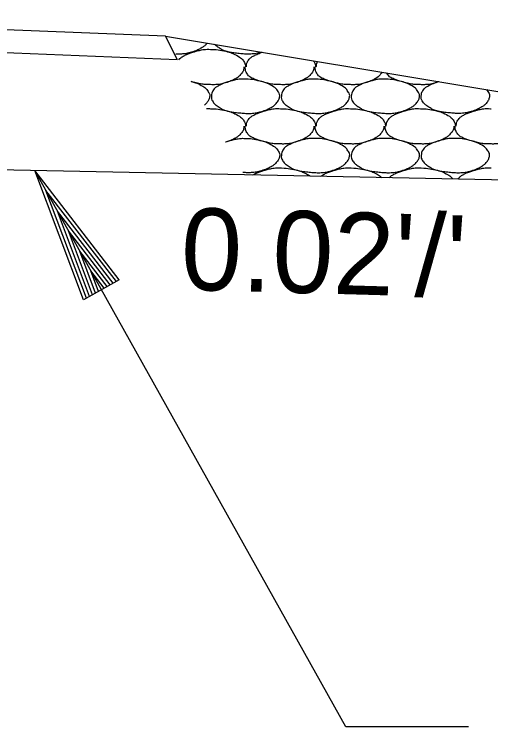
# Model space of a CAD drawing. Extents: x -900 to 15312, y 1857 to 2945.
# Drawn here: x 4203.1 to 4238, y 2407.3 to 2459.5 of the extents above; entities that cross this region are included whole.
import ezdxf

# ---------------------------------------------------------------- set-up
doc = ezdxf.new("R2010")
doc.units = 0
doc.layers.add('R_Annotation', color=7, linetype='Continuous')
doc.layers.add('R_Dimension', color=7, linetype='Continuous')

msp = doc.modelspace()

# ---------------------------------------------------------------- linework, layer by layer
at = {"layer": 'R_Annotation'}
for p, q in [((4214.164, 2457.891), (4174.164, 2459.491)), ((4214.164, 2457.891), (4215.015, 2456.189)), ((4214.164, 2457.891), (4374.164, 2431.224)), ((4282.587, 2446.487), (4064.164, 2450.856))]:
    msp.add_line(p, q, dxfattribs=at)
for points in [[(4217.21, 2457.383), (4217.184, 2457.347), (4217.061, 2457.195), (4216.938, 2457.101), (4216.622, 2456.922), (4216.424, 2456.826), (4215.92, 2456.667), (4215.636, 2456.595), (4215.199, 2456.568), (4215.054, 2456.567), (4214.909, 2456.576)], [(4221.199, 2456.718), (4220.957, 2456.647), (4220.714, 2456.592), (4220.317, 2456.567), (4219.95, 2456.577), (4219.584, 2456.612), (4219.122, 2456.663), (4218.883, 2456.701), (4218.448, 2456.802), (4218.279, 2456.907), (4217.97, 2457.101), (4217.853, 2457.183), (4217.748, 2457.294)], [(4215.144, 2456.163), (4215.25, 2456.298), (4215.379, 2456.381), (4215.656, 2456.525), (4215.785, 2456.59), (4216.123, 2456.704), (4216.321, 2456.764), (4216.65, 2456.849), (4216.958, 2456.921), (4217.278, 2456.933), (4217.464, 2456.917)], [(4217.464, 2456.917), (4217.484, 2456.915), (4217.504, 2456.918), (4217.524, 2456.917)], [(4217.524, 2456.917), (4217.817, 2456.921), (4218.111, 2456.876), (4218.762, 2456.743), (4219.092, 2456.635), (4219.645, 2456.338), (4219.822, 2456.183), (4219.996, 2455.859), (4220.016, 2455.76), (4220.024, 2455.65), (4220.025, 2455.643), (4220.024, 2455.637)], [(4220.084, 2455.637), (4220.084, 2455.643), (4220.086, 2455.819), (4220.135, 2455.987), (4220.354, 2456.288), (4220.49, 2456.376), (4220.776, 2456.525), (4220.905, 2456.59), (4221.117, 2456.661), (4221.19, 2456.685), (4221.263, 2456.708)], [(4224.982, 2456.088), (4225.011, 2456.047), (4225.107, 2455.907), (4225.136, 2455.76), (4225.144, 2455.65), (4225.145, 2455.643), (4225.144, 2455.637)], [(4219.904, 2455.637), (4219.904, 2455.617), (4219.909, 2455.391), (4219.768, 2455.198), (4219.533, 2454.935), (4219.438, 2454.861), (4219.122, 2454.682), (4218.924, 2454.586), (4218.42, 2454.427), (4218.137, 2454.348), (4217.717, 2454.332), (4217.59, 2454.331), (4217.464, 2454.337)], [(4222.584, 2454.337), (4222.557, 2454.337), (4222.31, 2454.334), (4222.063, 2454.357), (4221.61, 2454.439), (4221.387, 2454.51), (4220.964, 2454.632), (4220.774, 2454.695), (4220.372, 2454.868), (4220.196, 2455.021), (4220.026, 2455.347), (4220.004, 2455.46), (4220.004, 2455.597), (4220.004, 2455.617), (4220.004, 2455.637)], [(4225.024, 2455.637), (4225.024, 2455.617), (4225.029, 2455.391), (4224.888, 2455.198), (4224.653, 2454.935), (4224.558, 2454.861), (4224.242, 2454.682), (4224.044, 2454.586), (4223.54, 2454.427), (4223.257, 2454.348), (4222.837, 2454.332), (4222.71, 2454.331), (4222.584, 2454.337)], [(4227.704, 2454.337), (4227.677, 2454.337), (4227.43, 2454.334), (4227.183, 2454.357), (4226.73, 2454.439), (4226.507, 2454.51), (4226.084, 2454.632), (4225.894, 2454.695), (4225.492, 2454.868), (4225.316, 2455.021), (4225.146, 2455.347), (4225.124, 2455.46), (4225.124, 2455.597), (4225.124, 2455.617), (4225.124, 2455.637)], [(4225.204, 2455.637), (4225.204, 2455.643), (4225.205, 2455.781), (4225.236, 2455.915), (4225.3, 2456.035)], [(4230.028, 2455.247), (4229.981, 2455.174), (4229.924, 2455.104), (4229.773, 2454.935), (4229.678, 2454.861), (4229.362, 2454.682), (4229.164, 2454.586), (4228.66, 2454.427), (4228.377, 2454.348), (4227.957, 2454.332), (4227.83, 2454.331), (4227.704, 2454.337)], [(4232.824, 2454.337), (4232.797, 2454.337), (4232.55, 2454.334), (4232.303, 2454.357), (4231.85, 2454.439), (4231.627, 2454.51), (4231.204, 2454.632), (4231.014, 2454.695), (4230.626, 2454.861), (4230.46, 2455), (4230.347, 2455.194)], [(4216.044, 2454.576), (4216.304, 2454.506), (4216.554, 2454.411), (4217.025, 2454.158), (4217.177, 2453.997), (4217.387, 2453.682), (4217.421, 2453.572), (4217.37, 2453.289), (4217.272, 2453.102), (4217.092, 2452.901), (4217.06, 2452.869), (4217.028, 2452.84)], [(4217.464, 2454.337), (4217.437, 2454.337), (4217.19, 2454.334), (4216.943, 2454.357), (4216.492, 2454.438), (4216.27, 2454.509), (4216.044, 2454.574)], [(4220.024, 2454.737), (4220.317, 2454.741), (4220.611, 2454.696), (4221.262, 2454.563), (4221.592, 2454.455), (4222.145, 2454.158), (4222.297, 2453.997), (4222.507, 2453.682), (4222.541, 2453.572), (4222.49, 2453.289), (4222.392, 2453.102), (4222.15, 2452.832), (4222.058, 2452.761), (4221.742, 2452.582), (4221.544, 2452.486), (4221.04, 2452.327), (4220.756, 2452.255), (4220.317, 2452.227), (4219.95, 2452.237), (4219.584, 2452.272), (4219.122, 2452.323), (4218.883, 2452.361), (4218.448, 2452.462), (4218.279, 2452.567), (4217.905, 2452.801), (4217.744, 2452.922), (4217.532, 2453.247), (4217.517, 2453.365), (4217.533, 2453.639), (4217.567, 2453.802), (4217.802, 2454.113), (4217.93, 2454.196), (4218.216, 2454.345), (4218.345, 2454.41), (4218.683, 2454.524), (4218.881, 2454.584), (4219.21, 2454.669), (4219.518, 2454.741), (4219.838, 2454.753), (4220.024, 2454.737)], [(4225.144, 2454.737), (4225.437, 2454.741), (4225.731, 2454.696), (4226.382, 2454.563), (4226.712, 2454.455), (4227.265, 2454.158), (4227.417, 2453.997), (4227.627, 2453.682), (4227.661, 2453.572), (4227.61, 2453.289), (4227.512, 2453.102), (4227.27, 2452.832), (4227.178, 2452.761), (4226.862, 2452.582), (4226.664, 2452.486), (4226.16, 2452.327), (4225.876, 2452.255), (4225.437, 2452.227), (4225.07, 2452.237), (4224.704, 2452.272), (4224.242, 2452.323), (4224.003, 2452.361), (4223.568, 2452.462), (4223.399, 2452.567), (4223.025, 2452.801), (4222.864, 2452.922), (4222.652, 2453.247), (4222.637, 2453.365), (4222.653, 2453.639), (4222.687, 2453.802), (4222.922, 2454.113), (4223.05, 2454.196), (4223.336, 2454.345), (4223.465, 2454.41), (4223.803, 2454.524), (4224.001, 2454.584), (4224.33, 2454.669), (4224.638, 2454.741), (4224.958, 2454.753), (4225.144, 2454.737)], [(4230.264, 2454.737), (4230.557, 2454.741), (4230.851, 2454.696), (4231.502, 2454.563), (4231.832, 2454.455), (4232.385, 2454.158), (4232.537, 2453.997), (4232.747, 2453.682), (4232.781, 2453.572), (4232.73, 2453.289), (4232.632, 2453.102), (4232.39, 2452.832), (4232.298, 2452.761), (4231.982, 2452.582), (4231.784, 2452.486), (4231.28, 2452.327), (4230.996, 2452.255), (4230.557, 2452.227), (4230.19, 2452.237), (4229.824, 2452.272), (4229.362, 2452.323), (4229.123, 2452.361), (4228.688, 2452.462), (4228.519, 2452.567), (4228.145, 2452.801), (4227.984, 2452.922), (4227.772, 2453.247), (4227.757, 2453.365), (4227.773, 2453.639), (4227.807, 2453.802), (4228.042, 2454.113), (4228.17, 2454.196), (4228.456, 2454.345), (4228.585, 2454.41), (4228.923, 2454.524), (4229.121, 2454.584), (4229.45, 2454.669), (4229.758, 2454.741), (4230.078, 2454.753), (4230.264, 2454.737)], [(4234.177, 2454.555), (4234.14, 2454.542), (4233.818, 2454.438), (4233.497, 2454.348), (4233.077, 2454.332), (4232.95, 2454.331), (4232.824, 2454.337)], [(4237.655, 2453.976), (4237.706, 2453.916), (4237.755, 2453.849), (4237.867, 2453.682), (4237.901, 2453.572), (4237.85, 2453.289), (4237.752, 2453.102), (4237.51, 2452.832), (4237.418, 2452.761), (4237.102, 2452.582), (4236.904, 2452.486), (4236.4, 2452.327), (4236.116, 2452.255), (4235.677, 2452.227), (4235.31, 2452.237), (4234.944, 2452.272), (4234.482, 2452.323), (4234.243, 2452.361), (4233.808, 2452.462), (4233.639, 2452.567), (4233.265, 2452.801), (4233.104, 2452.922), (4232.892, 2453.247), (4232.877, 2453.365), (4232.893, 2453.639), (4232.927, 2453.802), (4233.162, 2454.113), (4233.29, 2454.196), (4233.576, 2454.345), (4233.705, 2454.41), (4233.95, 2454.492), (4234.056, 2454.526), (4234.162, 2454.558)], [(4217.173, 2452.583), (4217.27, 2452.587), (4217.368, 2452.585), (4217.464, 2452.577)], [(4217.464, 2452.577), (4217.484, 2452.575), (4217.504, 2452.578), (4217.524, 2452.577)], [(4217.524, 2452.577), (4217.817, 2452.581), (4218.111, 2452.536), (4218.762, 2452.403), (4219.092, 2452.295), (4219.645, 2451.998), (4219.822, 2451.843), (4219.996, 2451.519), (4220.016, 2451.42), (4220.024, 2451.31), (4220.025, 2451.303), (4220.024, 2451.297)], [(4220.084, 2451.297), (4220.084, 2451.303), (4220.086, 2451.479), (4220.135, 2451.647), (4220.354, 2451.948), (4220.49, 2452.036), (4220.776, 2452.185), (4220.905, 2452.25), (4221.243, 2452.364), (4221.441, 2452.424), (4221.77, 2452.509), (4222.078, 2452.581), (4222.398, 2452.593), (4222.584, 2452.577)], [(4222.584, 2452.577), (4222.604, 2452.575), (4222.624, 2452.578), (4222.644, 2452.577)], [(4222.644, 2452.577), (4222.937, 2452.581), (4223.231, 2452.536), (4223.882, 2452.403), (4224.212, 2452.295), (4224.765, 2451.998), (4224.942, 2451.843), (4225.116, 2451.519), (4225.136, 2451.42), (4225.144, 2451.31), (4225.145, 2451.303), (4225.144, 2451.297)], [(4225.204, 2451.297), (4225.204, 2451.303), (4225.206, 2451.479), (4225.255, 2451.647), (4225.474, 2451.948), (4225.61, 2452.036), (4225.896, 2452.185), (4226.025, 2452.25), (4226.363, 2452.364), (4226.561, 2452.424), (4226.89, 2452.509), (4227.198, 2452.581), (4227.518, 2452.593), (4227.704, 2452.577)], [(4227.704, 2452.577), (4227.724, 2452.575), (4227.744, 2452.578), (4227.764, 2452.577)], [(4227.764, 2452.577), (4228.057, 2452.581), (4228.351, 2452.536), (4229.002, 2452.403), (4229.332, 2452.295), (4229.885, 2451.998), (4230.062, 2451.843), (4230.236, 2451.519), (4230.256, 2451.42), (4230.264, 2451.31), (4230.265, 2451.303), (4230.264, 2451.297)], [(4230.324, 2451.297), (4230.324, 2451.303), (4230.326, 2451.479), (4230.375, 2451.647), (4230.594, 2451.948), (4230.73, 2452.036), (4231.016, 2452.185), (4231.145, 2452.25), (4231.483, 2452.364), (4231.681, 2452.424), (4232.01, 2452.509), (4232.318, 2452.581), (4232.638, 2452.593), (4232.824, 2452.577)], [(4232.824, 2452.577), (4232.844, 2452.575), (4232.864, 2452.578), (4232.884, 2452.577)], [(4232.884, 2452.577), (4233.177, 2452.581), (4233.471, 2452.536), (4234.122, 2452.403), (4234.452, 2452.295), (4235.005, 2451.998), (4235.182, 2451.843), (4235.356, 2451.519), (4235.376, 2451.42), (4235.384, 2451.31), (4235.385, 2451.303), (4235.384, 2451.297)], [(4235.444, 2451.297), (4235.444, 2451.303), (4235.446, 2451.479), (4235.495, 2451.647), (4235.714, 2451.948), (4235.85, 2452.036), (4236.136, 2452.185), (4236.265, 2452.25), (4236.603, 2452.364), (4236.801, 2452.424), (4237.13, 2452.509), (4237.438, 2452.581), (4237.758, 2452.593), (4237.944, 2452.577)], [(4237.944, 2452.577), (4237.964, 2452.575), (4237.984, 2452.578), (4238.004, 2452.577)], [(4219.904, 2451.297), (4219.904, 2451.277), (4219.909, 2451.051), (4219.768, 2450.858), (4219.533, 2450.595), (4219.438, 2450.521), (4219.122, 2450.342), (4218.924, 2450.246), (4218.657, 2450.162), (4218.61, 2450.147), (4218.563, 2450.133)], [(4222.584, 2449.997), (4222.557, 2449.997), (4222.31, 2449.994), (4222.063, 2450.017), (4221.61, 2450.099), (4221.387, 2450.17), (4220.964, 2450.292), (4220.774, 2450.355), (4220.372, 2450.528), (4220.196, 2450.681), (4220.026, 2451.007), (4220.004, 2451.12), (4220.004, 2451.257), (4220.004, 2451.277), (4220.004, 2451.297)], [(4225.024, 2451.297), (4225.024, 2451.277), (4225.029, 2451.051), (4224.888, 2450.858), (4224.653, 2450.595), (4224.558, 2450.521), (4224.242, 2450.342), (4224.044, 2450.246), (4223.54, 2450.087), (4223.257, 2450.008), (4222.837, 2449.992), (4222.71, 2449.991), (4222.584, 2449.997)], [(4227.704, 2449.997), (4227.677, 2449.997), (4227.43, 2449.994), (4227.183, 2450.017), (4226.73, 2450.099), (4226.507, 2450.17), (4226.084, 2450.292), (4225.894, 2450.355), (4225.492, 2450.528), (4225.316, 2450.681), (4225.146, 2451.007), (4225.124, 2451.12), (4225.124, 2451.257), (4225.124, 2451.277), (4225.124, 2451.297)], [(4230.144, 2451.297), (4230.144, 2451.277), (4230.149, 2451.051), (4230.008, 2450.858), (4229.773, 2450.595), (4229.678, 2450.521), (4229.362, 2450.342), (4229.164, 2450.246), (4228.66, 2450.087), (4228.377, 2450.008), (4227.957, 2449.992), (4227.83, 2449.991), (4227.704, 2449.997)], [(4232.824, 2449.997), (4232.797, 2449.997), (4232.55, 2449.994), (4232.303, 2450.017), (4231.85, 2450.099), (4231.627, 2450.17), (4231.204, 2450.292), (4231.014, 2450.355), (4230.612, 2450.528), (4230.436, 2450.681), (4230.266, 2451.007), (4230.244, 2451.12), (4230.244, 2451.257), (4230.244, 2451.277), (4230.244, 2451.297)], [(4235.264, 2451.297), (4235.264, 2451.277), (4235.269, 2451.051), (4235.128, 2450.858), (4234.893, 2450.595), (4234.798, 2450.521), (4234.482, 2450.342), (4234.284, 2450.246), (4233.78, 2450.087), (4233.497, 2450.008), (4233.077, 2449.992), (4232.95, 2449.991), (4232.824, 2449.997)], [(4237.944, 2449.997), (4237.917, 2449.997), (4237.67, 2449.994), (4237.423, 2450.017), (4236.97, 2450.099), (4236.747, 2450.17), (4236.324, 2450.292), (4236.134, 2450.355), (4235.732, 2450.528), (4235.556, 2450.681), (4235.386, 2451.007), (4235.364, 2451.12), (4235.364, 2451.257), (4235.364, 2451.277), (4235.364, 2451.297)], [(4240.384, 2451.297), (4240.384, 2451.277), (4240.389, 2451.051), (4240.248, 2450.858), (4240.013, 2450.595), (4239.918, 2450.521), (4239.602, 2450.342), (4239.404, 2450.246), (4238.9, 2450.087), (4238.617, 2450.008), (4238.197, 2449.992), (4238.07, 2449.991), (4237.944, 2449.997)], [(4218.558, 2450.141), (4218.732, 2450.198), (4219.032, 2450.291), (4219.335, 2450.357), (4219.649, 2450.406), (4219.838, 2450.413), (4220.024, 2450.397)], [(4220.024, 2450.397), (4220.317, 2450.401), (4220.611, 2450.356), (4221.262, 2450.223), (4221.592, 2450.115), (4222.145, 2449.818), (4222.297, 2449.657), (4222.507, 2449.342), (4222.541, 2449.232), (4222.49, 2448.949), (4222.392, 2448.762), (4222.15, 2448.492), (4222.058, 2448.421), (4221.742, 2448.242), (4221.544, 2448.146), (4221.04, 2447.987), (4220.756, 2447.915), (4220.317, 2447.887), (4220.103, 2447.89), (4219.889, 2447.906), (4219.822, 2447.912)], [(4225.144, 2450.397), (4225.437, 2450.401), (4225.731, 2450.356), (4226.382, 2450.223), (4226.712, 2450.115), (4227.265, 2449.818), (4227.417, 2449.657), (4227.627, 2449.342), (4227.661, 2449.232), (4227.61, 2448.949), (4227.512, 2448.762), (4227.27, 2448.492), (4227.178, 2448.421), (4226.862, 2448.242), (4226.664, 2448.146), (4226.16, 2447.987), (4225.876, 2447.915), (4225.437, 2447.887), (4225.07, 2447.897), (4224.704, 2447.932), (4224.242, 2447.983), (4224.003, 2448.021), (4223.568, 2448.122), (4223.399, 2448.227), (4223.025, 2448.461), (4222.864, 2448.582), (4222.652, 2448.907), (4222.637, 2449.025), (4222.653, 2449.299), (4222.687, 2449.462), (4222.922, 2449.773), (4223.05, 2449.856), (4223.336, 2450.005), (4223.465, 2450.07), (4223.803, 2450.184), (4224.001, 2450.244), (4224.33, 2450.329), (4224.638, 2450.401), (4224.958, 2450.413), (4225.144, 2450.397)], [(4230.264, 2450.397), (4230.557, 2450.401), (4230.851, 2450.356), (4231.502, 2450.223), (4231.832, 2450.115), (4232.385, 2449.818), (4232.537, 2449.657), (4232.747, 2449.342), (4232.781, 2449.232), (4232.73, 2448.949), (4232.632, 2448.762), (4232.39, 2448.492), (4232.298, 2448.421), (4231.982, 2448.242), (4231.784, 2448.146), (4231.28, 2447.987), (4230.996, 2447.915), (4230.557, 2447.887), (4230.19, 2447.897), (4229.824, 2447.932), (4229.362, 2447.983), (4229.123, 2448.021), (4228.688, 2448.122), (4228.519, 2448.227), (4228.145, 2448.461), (4227.984, 2448.582), (4227.772, 2448.907), (4227.757, 2449.025), (4227.773, 2449.299), (4227.807, 2449.462), (4228.042, 2449.773), (4228.17, 2449.856), (4228.456, 2450.005), (4228.585, 2450.07), (4228.923, 2450.184), (4229.121, 2450.244), (4229.45, 2450.329), (4229.758, 2450.401), (4230.078, 2450.413), (4230.264, 2450.397)], [(4235.384, 2450.397), (4235.677, 2450.401), (4235.971, 2450.356), (4236.622, 2450.223), (4236.952, 2450.115), (4237.505, 2449.818), (4237.657, 2449.657), (4237.867, 2449.342), (4237.901, 2449.232), (4237.85, 2448.949), (4237.752, 2448.762), (4237.51, 2448.492), (4237.418, 2448.421), (4237.102, 2448.242), (4236.904, 2448.146), (4236.4, 2447.987), (4236.116, 2447.915), (4235.677, 2447.887), (4235.31, 2447.897), (4234.944, 2447.932), (4234.482, 2447.983), (4234.243, 2448.021), (4233.808, 2448.122), (4233.639, 2448.227), (4233.265, 2448.461), (4233.104, 2448.582), (4232.892, 2448.907), (4232.877, 2449.025), (4232.893, 2449.299), (4232.927, 2449.462), (4233.162, 2449.773), (4233.29, 2449.856), (4233.576, 2450.005), (4233.705, 2450.07), (4234.043, 2450.184), (4234.241, 2450.244), (4234.57, 2450.329), (4234.878, 2450.401), (4235.198, 2450.413), (4235.384, 2450.397)], [(4220.555, 2447.728), (4220.584, 2447.745), (4220.746, 2447.83), (4220.905, 2447.91), (4221.243, 2448.024), (4221.441, 2448.084), (4221.77, 2448.169), (4222.078, 2448.241), (4222.398, 2448.253), (4222.584, 2448.237)], [(4225.528, 2447.628), (4225.601, 2447.686), (4225.813, 2447.804), (4226.025, 2447.91), (4226.363, 2448.024), (4226.561, 2448.084), (4226.89, 2448.169), (4227.198, 2448.241), (4227.518, 2448.253), (4227.704, 2448.237)], [(4230.542, 2447.528), (4230.64, 2447.638), (4230.756, 2447.71), (4231.016, 2447.845), (4231.145, 2447.91), (4231.483, 2448.024), (4231.681, 2448.084), (4232.01, 2448.169), (4232.318, 2448.241), (4232.638, 2448.253), (4232.824, 2448.237)], [(4235.583, 2447.427), (4235.59, 2447.437), (4235.705, 2447.602), (4235.85, 2447.696), (4236.136, 2447.845), (4236.265, 2447.91), (4236.603, 2448.024), (4236.801, 2448.084), (4237.13, 2448.169), (4237.438, 2448.241), (4237.758, 2448.253), (4237.944, 2448.237)], [(4222.584, 2448.237), (4222.604, 2448.235), (4222.624, 2448.238), (4222.644, 2448.237)], [(4222.644, 2448.237), (4222.937, 2448.241), (4223.231, 2448.196), (4223.882, 2448.063), (4224.212, 2447.955), (4224.618, 2447.737), (4224.687, 2447.693), (4224.751, 2447.644)], [(4227.704, 2448.237), (4227.724, 2448.235), (4227.744, 2448.238), (4227.764, 2448.237)], [(4227.764, 2448.237), (4228.057, 2448.241), (4228.351, 2448.196), (4229.002, 2448.063), (4229.332, 2447.955), (4229.787, 2447.711), (4229.896, 2447.633), (4229.99, 2447.539)], [(4232.824, 2448.237), (4232.844, 2448.235), (4232.864, 2448.238), (4232.884, 2448.237)], [(4232.884, 2448.237), (4233.177, 2448.241), (4233.471, 2448.196), (4234.122, 2448.063), (4234.452, 2447.955), (4234.95, 2447.688), (4235.09, 2447.579), (4235.202, 2447.435)], [(4237.944, 2448.237), (4237.964, 2448.235), (4237.984, 2448.238), (4238.004, 2448.237)]]:
    msp.add_open_spline(points, degree=3, dxfattribs=at)
at = {"layer": 'R_Dimension'}
for p, q in [((4214.164, 2457.891), (4174.164, 2459.491)), ((4175.015, 2457.789), (4215.015, 2456.189)), ((4215.015, 2456.189), (4214.164, 2457.891)), ((4210.782, 2440.051), (4204.592, 2448.047)), ((4208.163, 2438.587), (4204.592, 2448.047)), ((4210.564, 2439.929), (4205.407, 2446.589)), ((4208.382, 2438.709), (4205.407, 2446.589)), ((4208.604, 2438.833), (4206.246, 2445.088)), ((4210.341, 2439.805), (4206.246, 2445.088)), ((4210.123, 2439.683), (4207.059, 2443.635)), ((4208.822, 2438.956), (4207.059, 2443.635)), ((4209.045, 2439.08), (4207.886, 2442.156)), ((4209.896, 2439.556), (4207.886, 2442.156)), ((4209.267, 2439.204), (4208.701, 2440.698)), ((4209.678, 2439.434), (4208.701, 2440.698)), ((4210.782, 2440.051), (4208.163, 2438.587))]:
    msp.add_line(p, q, dxfattribs=at)
msp.add_lwpolyline([(4236.351, 2407.334), (4227.362, 2407.334), (4204.592, 2448.047)], dxfattribs=at)

# ---------------------------------------------------------------- texts
at = {"layer": 'R_Annotation'}
msp.add_text("0.02'/'", height=6, rotation=358.3978, dxfattribs=at).set_placement((4215.228, 2439.337))

doc.saveas('drawing.dxf')
